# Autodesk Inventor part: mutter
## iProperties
Author: Jørgen Albe Bjørnes
Shininess: 25.0
PropertySet Name: _Private Model Information
Created: 2001-01
Part Number: mutter
Document SubType Name: Modeling
Designer: Jørgen Albe Bjørnes
Material: 8
Description: Hex Locking nut M8
Vendor: DIN 985 / DIN EN ISO 10511
Control State: 0
Master: False
Checked Out: False
PropertySet Name: Design Tracking Control
Density: 0.0
Volumn: 0.0
Area: 0.0
PropertySet Name: Model Information
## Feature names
1. Hole2
2. Revolution1
3. Mirror1
4. Extrusion3
5. Extrusion1
